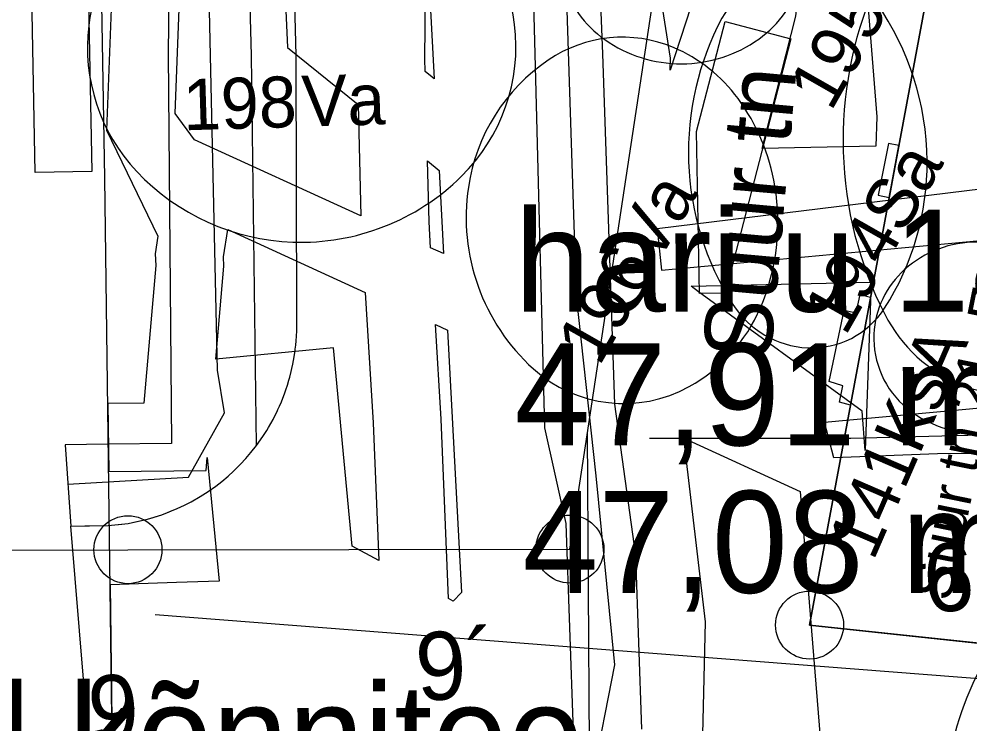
# Model space of a CAD drawing. Extents: x 738423 to 738903, y 6589762 to 6590172.
# Drawn here: x 738562.92 to 738590.9, y 6589869.71 to 6589890.45 of the extents above; entities that cross this region are included whole.
import ezdxf

# ---------------------------------------------------------------- set-up
doc = ezdxf.new("R2010")
doc.units = 0
for name, color, linetype in [('_1927_hoonestus', 7, 'Continuous'), ('_1927_katuse_kalded', 7, 'Continuous'), ('_1927_koordin_punktid_nr', 7, 'Continuous'), ('_1927_krundi_piir', 7, 'Continuous'), ('_a_ajalooline_maapind', 7, 'Continuous'), ('_a_olol_maapind', 7, 'Continuous'), ('_ajalooline_aadress', 7, 'Continuous'), ('a_', 7, 'Continuous'), ('a_dendro_II_Vkl_puu', 7, 'Continuous'), ('a_dendro_III_vk_puu', 7, 'Continuous'), ('a_dendro_puu_nr', 7, 'Continuous'), ('Default', 7, 'Continuous'), ('plan_ala', 7, 'Continuous'), ('v_dp_jalak_liikumine', 7, 'Continuous'), ('v_dp_tehno_sund', 7, 'Continuous'), ('v_olol_hoone', 7, 'Continuous'), ('v_olol_kitsendus_tehnov', 7, 'Continuous'), ('v_olol_transp_jjt_jalg', 7, 'Continuous'), ('v_olol_transp_tee', 7, 'Continuous')]:
    doc.layers.add(name, color=color, linetype=linetype)

# ---------------------------------------------------------------- blocks, each defined once
blk = doc.blocks.new('_U589')
at = {"layer": 'Default'}
for centre, radius, start, end in [((-3.0332052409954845e-05, -0.002338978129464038), 0.01836532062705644, 93.86605779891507, 141.50719662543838), ((-4.742218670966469e-05, -0.0020860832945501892), 0.018111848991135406, 48.095809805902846, 93.86605779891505), ((0.00495080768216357, 0.003483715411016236), 0.010628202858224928, 347.0797159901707, 48.09580980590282), ((-0.006053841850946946, 0.0024511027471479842), 0.01066937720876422, 141.5071966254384, 205.50153110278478), ((0.003081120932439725, 0.003912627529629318), 0.012546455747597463, 307.30050710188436, 347.0797159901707), ((-0.004183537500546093, 0.0033432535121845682), 0.012741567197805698, 205.50153110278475, 244.5264522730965), ((-0.0011840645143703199, 0.009511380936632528), 0.019584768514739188, 275.69820016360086, 307.30050710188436), ((-0.0011946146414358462, 0.009617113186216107), 0.019691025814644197, 244.52645227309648, 275.69820016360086)]:
    blk.add_arc(centre, radius, start, end, dxfattribs=at)
blk = doc.blocks.new('_U591')
at = {"layer": 'Default'}
for centre, radius, start, end in [((-0.0003541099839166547, 0.0006764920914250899), 0.005338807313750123, 91.75356257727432, 144.94764571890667), ((-0.00035206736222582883, 0.0006097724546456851), 0.0054055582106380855, 45.990503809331, 91.75356257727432), ((-0.001037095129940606, -9.935932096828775e-05), 0.006391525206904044, 4.0870855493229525, 45.99050380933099), ((0.0005026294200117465, 7.542928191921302e-05), 0.006385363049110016, 144.94764571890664, 193.2797082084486), ((-0.0009608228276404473, -9.390933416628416e-05), 0.00631505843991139, 322.4423423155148, 4.08708554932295), ((0.00038141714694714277, 4.682123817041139e-05), 0.006260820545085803, 193.27970820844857, 233.32322588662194), ((-0.00018547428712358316, -0.0006900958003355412), 0.005336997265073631, 276.9468734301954, 322.4423423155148), ((-0.0001829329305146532, -0.000710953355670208), 0.0053159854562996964, 233.3232258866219, 276.9468734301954)]:
    blk.add_arc(centre, radius, start, end, dxfattribs=at)
blk = doc.blocks.new('_U643')
at = {"layer": 'Default'}
for centre, radius, start, end in [((0.001839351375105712, -0.01638537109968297), 0.02252182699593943, 96.00680549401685, 121.28846409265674), ((0.0018679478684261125, -0.01665713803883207), 0.02279509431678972, 71.14771462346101, 96.00680549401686), ((0.0062500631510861, -0.0038231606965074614), 0.009233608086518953, 31.614909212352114, 71.14771462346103), ((-0.005254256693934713, -0.004713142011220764), 0.008863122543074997, 121.28846409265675, 162.12182872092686), ((0.009030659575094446, -0.0021115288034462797), 0.005968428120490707, 314.530794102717, 31.614909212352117), ((-0.008067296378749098, -0.00380573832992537), 0.00590735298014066, 162.12182872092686, 235.6485071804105), ((-0.000617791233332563, 0.007696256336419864), 0.019726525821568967, 274.44396782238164, 314.530794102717), ((-0.0005757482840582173, 0.0071552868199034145), 0.019183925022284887, 235.6485071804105, 274.44396782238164)]:
    blk.add_arc(centre, radius, start, end, dxfattribs=at)
blk = doc.blocks.new('_U644')
at = {"layer": 'Default'}
for centre, radius, start, end in [((0.001280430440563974, -0.010476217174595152), 0.01658674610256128, 96.22277175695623, 126.90463232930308), ((0.00130196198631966, -0.010673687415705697), 0.016785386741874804, 66.2630147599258, 96.22277175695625), ((0.005749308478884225, -0.0005600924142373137), 0.005737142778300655, 13.784006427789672, 66.26301475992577), ((-0.005344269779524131, -0.001654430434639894), 0.005554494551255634, 126.90463232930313, 181.31501957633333), ((0.006382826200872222, -0.0004046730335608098), 0.005084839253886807, 309.3713168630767, 13.784006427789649), ((-0.00581699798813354, -0.001665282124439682), 0.005081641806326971, 181.3150195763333, 241.68386791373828), ((-0.0007414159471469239, 0.008277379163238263), 0.01631572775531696, 274.75209171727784, 309.37131686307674), ((-0.000703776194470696, 0.007824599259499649), 0.015861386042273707, 241.68386791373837, 274.75209171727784)]:
    blk.add_arc(centre, radius, start, end, dxfattribs=at)
blk = doc.blocks.new('_U645')
at = {"layer": 'Default'}
for centre, radius, start, end in [((-0.001848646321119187, 2.996627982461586e-05), 0.011998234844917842, 85.79154951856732, 142.2176902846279), ((-0.0017770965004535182, 0.0010023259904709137), 0.01102324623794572, 38.521789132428, 85.79154951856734), ((0.0007803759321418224, 0.003038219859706), 0.007754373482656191, 341.41250812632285, 38.521789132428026), ((-0.005054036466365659, 0.0025147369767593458), 0.0079425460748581, 142.21769028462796, 213.26626182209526), ((-0.00046359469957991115, 0.0034565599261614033), 0.009066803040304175, 310.5147127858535, 341.41250812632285), ((-0.003640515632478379, 0.003442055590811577), 0.00963309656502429, 213.2662618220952, 251.166227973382), ((-0.0024438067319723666, 0.0057738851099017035), 0.0121149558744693, 283.86825920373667, 310.5147127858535), ((-0.0026123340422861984, 0.006456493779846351), 0.01281806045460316, 251.16622797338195, 283.86825920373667)]:
    blk.add_arc(centre, radius, start, end, dxfattribs=at)
blk = doc.blocks.new('_U646')
at = {"layer": 'Default'}
for centre, radius, start, end in [((0.0015413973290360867, 0.0003312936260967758), 0.0060430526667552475, 57.797497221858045, 109.91963154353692), ((0.0016638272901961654, -6.553680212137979e-06), 0.006402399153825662, 109.91963154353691, 149.09162520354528), ((0.0007475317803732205, -0.000929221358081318), 0.007532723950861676, 11.452907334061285, 57.79749722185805), ((0.0028668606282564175, -0.000726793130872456), 0.007804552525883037, 149.09162520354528, 184.44182767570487), ((0.0005947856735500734, -0.0009601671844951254), 0.007688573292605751, 318.66315817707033, 11.452907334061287), ((0.0029452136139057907, -0.0007207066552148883), 0.00788314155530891, 184.44182767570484, 219.7138265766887), ((0.001892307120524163, -0.0015952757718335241), 0.006514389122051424, 219.71382657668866, 258.64991313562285), ((0.0018059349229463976, -0.002025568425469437), 0.006075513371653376, 258.64991313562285, 318.66315817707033)]:
    blk.add_arc(centre, radius, start, end, dxfattribs=at)
blk = doc.blocks.new('_U647')
at = {"layer": 'Default'}
for centre, radius, start, end in [((-0.001375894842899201, 0.00038972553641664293), 0.01064500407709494, 87.41040859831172, 137.64698014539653), ((-0.0013903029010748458, 7.115839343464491e-05), 0.01096389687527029, 46.91324083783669, 87.4104085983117), ((-0.003055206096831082, -0.0017088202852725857), 0.013401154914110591, 10.427707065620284, 46.91324083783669), ((0.0005566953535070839, -0.0013720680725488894), 0.013260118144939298, 137.64698014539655, 182.35571578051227), ((-0.0033161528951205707, -0.0017568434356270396), 0.013666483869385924, 328.31163123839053, 10.427707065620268), ((0.0007803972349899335, -0.0013628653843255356), 0.013484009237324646, 182.3557157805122, 228.78056258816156), ((-0.0010775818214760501, -0.003138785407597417), 0.011035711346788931, 281.1734997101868, 328.3116312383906), ((-0.0010219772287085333, -0.0034202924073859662), 0.010748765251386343, 228.7805625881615, 281.1734997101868)]:
    blk.add_arc(centre, radius, start, end, dxfattribs=at)

msp = doc.modelspace()

# ---------------------------------------------------------------- linework, layer by layer
at = {"layer": '_1927_hoonestus'}
for points in [[(738598.7561479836, 6589884.064893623), (738598.7561479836, 6589884.064893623), (738600.1654182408, 6589891.510843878), (738617.1576277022, 6589889.916511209), (738616.9587005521, 6589887.781161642), (738616.9587005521, 6589887.781161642), (738621.4793553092, 6589887.4869466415), (738621.2187353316, 6589884.178665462), (738631.1763472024, 6589883.225550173), (738634.3211426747, 6589909.080822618), (738624.2071897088, 6589909.313105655), (738622.5673353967, 6589895.324185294), (738590.9372064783, 6589898.13516685), (738590.9372064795, 6589898.13516685), (738586.1827055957, 6589872.62061175), (738613.3249623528, 6589869.722398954), (738613.2710881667, 6589869.728151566), (738614.3523733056, 6589877.812429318), (738614.3523733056, 6589877.812429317), (738614.3523733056, 6589877.812429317), (738615.0233334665, 6589882.235576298)], [(738588.8127019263, 6589886.73422492), (738588.5070185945, 6589886.794471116), (738588.1986895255, 6589885.274121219), (738588.527742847, 6589885.205020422)], [(738587.388382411, 6589879.090756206), (738587.0612662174, 6589879.175962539), (738587.1642145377, 6589879.657378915), (738586.7650323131, 6589879.784371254), (738587.1979710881, 6589881.885807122), (738587.5573741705, 6589881.811762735), (738587.6678450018, 6589882.347975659), (738587.9811086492, 6589882.271562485)]]:
    msp.add_lwpolyline(points, close=True, dxfattribs=at)
at = {"layer": '_1927_katuse_kalded'}
msp.add_lwpolyline([(738586.1827055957, 6589872.62061175), (738591.5884234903, 6589872.043396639), (738595.5346271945, 6589892.346110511), (738589.9993202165, 6589893.102093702)], close=True, dxfattribs=at)
at = {"layer": '_1927_koordin_punktid_nr'}
for centre in [(738566.1261897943, 6589874.839209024), (738579.1301963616, 6589874.856906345), (738586.182705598, 6589872.620611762)]:
    msp.add_circle(centre, 0.9999999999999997, dxfattribs=at)
at = {"layer": '_1927_krundi_piir'}
msp.add_line((738629.2817413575, 6589868.018556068), (738586.182705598, 6589872.620611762), dxfattribs=at)
for points in [[(738579.1301963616, 6589874.856906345), (738582.2977970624, 6589895.764005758), (738583.8997575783, 6589916.874257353), (738587.3009719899, 6589941.27260649), (738586.2348708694, 6589945.684910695), (738584.5188972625, 6589952.81209349)], [(738586.182705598, 6589872.620611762), (738590.9372064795, 6589898.13516685), (738590.975352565, 6589898.488217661), (738593.7110525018, 6589923.115674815), (738595.6482555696, 6589940.609766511), (738608.5799562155, 6589940.823351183), (738620.342268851, 6589941.795771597), (738638.2396178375, 6589940.94571321)], [(738456.3718778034, 6589873.590089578), (738496.3572965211, 6589874.745766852), (738517.6969158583, 6589874.771193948), (738536.6717751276, 6589874.799754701), (738566.1261897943, 6589874.839209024), (738579.1301963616, 6589874.856906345)]]:
    msp.add_lwpolyline(points, dxfattribs=at)
at = {"layer": 'a_'}
for p, q in [((738579.7240658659, 6589866.182764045), (738579.6493548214, 6589878.283505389)), ((738566.9298928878, 6589872.9281633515), (738595.2945655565, 6589870.727518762))]:
    msp.add_line(p, q, dxfattribs=at)
at = {"layer": 'Default'}
for points in [[(738581.2509999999, 6589869.558000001), (738581.073, 6589874.656), (738580.457, 6589879.119), (738580.1019999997, 6589889.433000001), (738579.5900000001, 6589902.219999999), (738580.555, 6589902.854999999), (738586.5010000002, 6589903.156999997), (738587.2448897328, 6589903.302988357), (738587.463427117, 6589905.386079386), (738586.2330000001, 6589905.318), (738580.2700000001, 6589904.839), (738579.4450000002, 6589905.446999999), (738579.2310000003, 6589922.173000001)], [(738577.3480000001, 6589920.061000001), (738577.716, 6589903.953000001), (738578.12, 6589888.683000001), (738578.3879999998, 6589878.424000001), (738579.014, 6589875.606999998), (738579.2310000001, 6589869.493000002)]]:
    msp.add_lwpolyline(points, dxfattribs=at)
at = {"layer": 'plan_ala'}
msp.add_lwpolyline([(738772.2221966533, 6589837.873120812), (738583.11, 6589865.669999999), (738583.11, 6589865.669999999), (738577.13, 6589865.85), (738565.7035831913, 6589866.139410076), (738565.4500000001, 6589885.77), (738564.4932191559, 6589941.052825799), (738581.9, 6589941.1499999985), (738615.11, 6589942.169999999), (738650.0499999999, 6589943.319999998), (738691.2690631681, 6589944.800325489), (738696.0901513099, 6589944.851371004), (738713.89, 6589945.129999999), (738703.51, 6589987.789999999), (738752.8799999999, 6590000.39), (738783.1408503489, 6590007.463828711), (738767.5688789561, 6589951.87996157)], close=True, dxfattribs=at)
at = {"layer": 'v_dp_jalak_liikumine'}
for points in [[(738580.8222069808, 6589853.375742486), (738579.8731274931, 6589862.502301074), (738579.7948247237, 6589868.094183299), (738580.455907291, 6589871.452329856), (738579.9085136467, 6589877.0110812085), (738579.325053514, 6589882.302804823), (738578.6922566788, 6589901.835364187), (738578.2534358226, 6589923.78491095), (738577.7643827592, 6589940.522382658), (738578.0100246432, 6589944.392285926), (738576.7151896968, 6589950.204053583)], [(738564.3587612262, 6589876.768792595), (738567.9129245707, 6589876.968967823), (738568.9682240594, 6589878.865942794), (738568.76067344, 6589880.123714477), (738568.2947477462, 6589901.299299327), (738567.7091425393, 6589926.873099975), (738566.992151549, 6589942.227474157), (738566.338151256, 6589947.998374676)], [(738581.4723412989, 6589878.120522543), (738587.4015406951, 6589878.120522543), (738606.5184403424, 6589878.608756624), (738618.5434188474, 6589878.425595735), (738641.8496480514, 6589878.136204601), (738655.9728153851, 6589879.813491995), (738670.3230528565, 6589879.497843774), (738680.5529887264, 6589878.338003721), (738697.9581193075, 6589880.397873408), (738705.6932562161, 6589881.082962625), (738725.5888177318, 6589880.833839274), (738742.0007790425, 6589880.833839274), (738745.4047050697, 6589880.7783847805), (738754.5304628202, 6589882.343075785), (738758.8441211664, 6589885.746853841)]]:
    msp.add_lwpolyline(points, dxfattribs=at)
at = {"layer": 'v_dp_tehno_sund'}
msp.add_lwpolyline([(738585.63220001, 6589889.873199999), (738583.6956, 6589882.391), (738582.94000001, 6589882.38), (738582.8558, 6589887.1405), (738583.6967, 6589890.3771)], close=True, dxfattribs=at)
at = {"layer": 'v_olol_hoone'}
msp.add_lwpolyline([(738563.1864886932, 6589896.902176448), (738564.8460000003, 6589896.936000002), (738565.0596708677, 6589885.967899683), (738563.3941039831, 6589885.935452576)], close=True, dxfattribs=at)
at = {"layer": 'v_olol_kitsendus_tehnov'}
for points in [[(738567.6884596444, 6589928.157698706), (738569.5640555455, 6589928.107424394), (738569.7442949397, 6589922.973568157), (738570.2308726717, 6589902.597054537), (738570.8235144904, 6589889.61800687), (738572.8972610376, 6589887.936315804), (738572.9818196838, 6589884.664234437), (738568.089969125, 6589886.902320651), (738567.5159941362, 6589887.676248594), (738567.8866814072, 6589897.433658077), (738567.9899137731, 6589898.018834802), (738568.721228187, 6589898.636862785), (738568.6597970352, 6589921.868076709)], [(738582.0806785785, 6589888.9498845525), (738582.0888304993, 6589889.297274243), (738581.1487846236, 6589895.290815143), (738581.3691582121, 6589899.835374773), (738582.3698831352, 6589899.926173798), (738582.3430488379, 6589901.192727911), (738583.3139503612, 6589901.241959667), (738583.6007202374, 6589893.6200148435)], [(738574.904547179, 6589893.1154798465), (738575.1393173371, 6589888.692995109), (738575.0823527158, 6589888.739309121), (738574.8727855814, 6589888.909256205), (738574.8631395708, 6589889.282518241)], [(738575.0337955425, 6589883.725428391), (738574.9872051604, 6589884.4816761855), (738574.9408154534, 6589886.276772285), (738575.2823234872, 6589885.999115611), (738575.4122142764, 6589883.552296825)], [(738572.1726483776, 6589880.774872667), (738568.713804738, 6589880.446204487), (738568.9528174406, 6589883.178554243), (738568.9351775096, 6589883.451973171), (738569.0649967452, 6589884.25685243), (738573.1113141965, 6589882.405608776), (738573.3472319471, 6589878.576228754), (738573.5098466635, 6589874.51818583), (738572.7267045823, 6589874.9440868)], [(738587.9947308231, 6589882.710662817), (738587.8201164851, 6589877.754352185), (738587.7269088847, 6589878.910557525), (738582.912444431, 6589882.422678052), (738582.6979742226, 6589882.5943622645)], [(738575.6968588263, 6589873.328809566), (738575.5560439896, 6589873.405389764), (738575.344768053, 6589878.677771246), (738575.1732233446, 6589881.462258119), (738575.5318759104, 6589881.298169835), (738575.9417934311, 6589873.576345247)]]:
    msp.add_lwpolyline(points, close=True, dxfattribs=at)
for points in [[(738564.7836066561, 6589924.311755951), (738565.5546792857, 6589898.442616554), (738565.977184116, 6589898.121736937), (738565.8933185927, 6589897.646341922), (738565.4958801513, 6589887.184775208), (738567.007573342, 6589884.061082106), (738566.9248224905, 6589883.548026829), (738566.9471825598, 6589883.201445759), (738566.5929069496, 6589879.151431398), (738565.5356253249, 6589879.141502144), (738565.5614588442, 6589877.14165656), (738568.4270930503, 6589877.168568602), (738568.4607498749, 6589877.553327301), (738568.8064016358, 6589873.915751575), (738567.5534011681, 6589873.878412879), (738565.6046055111, 6589873.801551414), (738565.6869613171, 6589867.426156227)], [(738591.66193984, 6589894.040728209), (738588.6389999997, 6589893.962), (738587.6660926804, 6589893.829031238), (738588.1662590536, 6589887.579376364), (738588.135796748, 6589886.714724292), (738584.7931808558, 6589886.641330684), (738585.7810944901, 6589890.54142003), (738586.1426695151, 6589893.750789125), (738586.0517247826, 6589901.380784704), (738588.4926106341, 6589901.504555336), (738588.4591681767, 6589903.227642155), (738587.933124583, 6589903.217432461), (738587.889229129, 6589905.479098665), (738585.9959303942, 6589905.383094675), (738585.9826741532, 6589905.560547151), (738587.8870005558, 6589905.593923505), (738587.8850000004, 6589905.697), (738588.4110435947, 6589905.707209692), (738588.3392058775, 6589909.602463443)], [(738582.957333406, 6589865.674595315), (738583.1203691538, 6589872.717573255), (738582.4794695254, 6589878.119554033), (738585.9107412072, 6589876.549701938), (738586.6978541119, 6589866.78586143)]]:
    msp.add_lwpolyline(points, dxfattribs=at)
at = {"layer": 'v_olol_transp_jjt_jalg'}
for points in [[(738581.2509999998, 6589869.558000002), (738581.073, 6589874.656), (738580.4569999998, 6589879.118999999), (738580.102, 6589889.433000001), (738579.5900000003, 6589902.219999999), (738580.555, 6589902.854999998), (738586.5010000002, 6589903.157000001), (738587.3010000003, 6589903.313999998), (738587.2610015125, 6589905.374879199), (738586.2329999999, 6589905.317999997), (738580.2699999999, 6589904.838999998), (738579.445, 6589905.446999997), (738579.2310000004, 6589922.1729999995)], [(738577.3479999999, 6589920.061), (738577.7159999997, 6589903.953), (738578.1199999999, 6589888.682999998), (738578.3879999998, 6589878.423999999), (738579.0140000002, 6589875.607), (738579.2310000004, 6589869.493000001)], [(738567.4200000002, 6589899.302000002), (738567.308, 6589889.425), (738567.4120000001, 6589877.964000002), (738565.5350274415, 6589877.942673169), (738564.2760718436, 6589877.9283684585), (738564.4467826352, 6589875.534444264), (738565.5440000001, 6589875.547000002), (738565.9454704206, 6589875.586374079), (738566.1317947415, 6589875.614088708), (738566.3931792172, 6589875.670514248), (738566.7004281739, 6589875.736840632), (738566.8687682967, 6589875.7887755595), (738567.1261730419, 6589875.868187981), (738567.2742066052, 6589875.926941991), (738567.4296404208, 6589875.988633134), (738567.5781354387, 6589876.047570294), (738567.791011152, 6589876.147440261), (738567.9871197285, 6589876.2488150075), (738568.2563765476, 6589876.403662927), (738568.4855327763, 6589876.550888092), (738568.7119822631, 6589876.711680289), (738568.8879156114, 6589876.848119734), (738569.0749685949, 6589877.005355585), (738569.2315573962, 6589877.147604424), (738569.3353643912, 6589877.250340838), (738569.4416940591, 6589877.355573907), (738569.5986054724, 6589877.525307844), (738569.743375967, 6589877.694454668), (738569.9119999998, 6589877.909), (738569.7619999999, 6589889.376999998), (738569.4820219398, 6589900.016635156)]]:
    msp.add_lwpolyline(points, dxfattribs=at)
for points in [[(738581.6950000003, 6589884.280999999), (738581.8219999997, 6589883.063999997), (738591.5299999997, 6589883.9679999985), (738608.3539999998, 6589886.010999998), (738615.5839999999, 6589886.649999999), (738615.4390000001, 6589888.155999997), (738608.0640000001, 6589887.33), (738591.8460000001, 6589885.529)], [(738608.1226609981, 6589880.056703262), (738609.449, 6589880.072000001), (738610.0780826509, 6589880.024413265), (738610.0780826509, 6589880.024413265), (738610.195, 6589876.471000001), (738608.6379999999, 6589876.482999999), (738608.6379999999, 6589876.482999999), (738608.2503136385, 6589876.487158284), (738608.2503136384, 6589876.487158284), (738608.1189999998, 6589877.699999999), (738608.1192188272, 6589877.747777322), (738589.9439999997, 6589877.660999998), (738586.8979999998, 6589877.539000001), (738586.624, 6589878.5869999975), (738594.5109999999, 6589879.317999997), (738602.754, 6589879.872), (738608.1242055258, 6589879.365527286)]]:
    msp.add_lwpolyline(points, close=True, dxfattribs=at)
at = {"layer": 'v_olol_transp_tee'}
for points in [[(738577.3479999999, 6589920.061), (738577.7159999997, 6589903.953), (738578.1199999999, 6589888.682999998), (738578.3879999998, 6589878.423999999), (738579.0140000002, 6589875.607), (738579.2310000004, 6589869.493000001)], [(738564.9604277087, 6589869.373161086), (738564.4467826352, 6589875.534444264), (738564.8583281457, 6589875.539153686), (738565.5439999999, 6589875.547), (738566.1317946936, 6589875.614088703), (738566.7004281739, 6589875.736840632), (738567.1261730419, 6589875.868187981), (738567.5781354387, 6589876.047570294), (738567.791011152, 6589876.147440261), (738567.9871197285, 6589876.2488150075), (738568.2563765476, 6589876.403662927), (738568.4855327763, 6589876.550888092), (738568.7119822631, 6589876.711680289), (738568.8879156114, 6589876.848119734), (738569.0749685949, 6589877.005355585), (738569.2315573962, 6589877.147604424), (738569.4416940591, 6589877.355573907), (738569.5986054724, 6589877.525307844), (738569.743375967, 6589877.694454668), (738569.9119999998, 6589877.909), (738570.0273962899, 6589878.068432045), (738570.1136574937, 6589878.1953384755), (738570.2117711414, 6589878.348852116), (738570.2640456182, 6589878.435112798), (738570.3305321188, 6589878.549862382), (738570.3958284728, 6589878.668671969), (738570.452323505, 6589878.776977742), (738570.5171491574, 6589878.908433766), (738570.5421125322, 6589878.961342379), (738570.5871630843, 6589879.060423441), (738570.6437903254, 6589879.192346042), (738570.684751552, 6589879.293679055), (738570.7342187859, 6589879.423840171), (738570.7762723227, 6589879.542406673), (738570.8204787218, 6589879.676555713), (738570.8653812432, 6589879.8252220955), (738570.8892277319, 6589879.910467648), (738570.9323083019, 6589880.078721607), (738570.9538449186, 6589880.171545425), (738570.9810588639, 6589880.299927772), (738571.0020215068, 6589880.409885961), (738571.02038953, 6589880.517032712), (738571.0392880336, 6589880.642121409), (738571.051721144, 6589880.736288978), (738571.0653998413, 6589880.856780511), (738571.0768989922, 6589880.981015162), (738571.0866724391, 6589881.120416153), (738571.0936776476, 6589881.275571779), (738571.0965060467, 6589881.415274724), (738571.0963368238, 6589881.532729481), (738571.0939999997, 6589881.644999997), (738571.0769999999, 6589889.378), (738570.8110000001, 6589899.744)]]:
    msp.add_lwpolyline(points, dxfattribs=at)

# ---------------------------------------------------------------- block references
at = {"layer": 'a_dendro_II_Vkl_puu', "xscale": 500.0000000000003, "yscale": 500.0000000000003, "rotation": 85.69234851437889}
msp.add_blockref('_U643', (738590.191, 6589886.574999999), dxfattribs=at)
at = {"layer": 'a_dendro_III_vk_puu', "xscale": 500.0000000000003, "yscale": 500.0000000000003, "rotation": 85.69234851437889}
for name, p in [('_U646', (738581.9369999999, 6589891.635)), ('_U647', (738570.5030000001, 6589890.29)), ('_U644', (738585.6409999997, 6589886.279)), ('_U645', (738582.1609999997, 6589885.537000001)), ('_U591', (738591.0953105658, 6589881.216442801)), ('_U589', (738598.176, 6589867.216))]:
    msp.add_blockref(name, p, dxfattribs=at)

# ---------------------------------------------------------------- texts
at = {"layer": '_1927_koordin_punktid_nr'}
for s, height, rotation, p in [('Suur tn', 1.9999999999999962, 84.83058672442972, (738585.023061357, 6589880.3657192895)), ('6', 1.9999999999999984, 3.560863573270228, (738589.5909850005, 6589872.985900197)), ('9´', 1.9999999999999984, 3.560863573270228, (738574.6550161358, 6589870.381702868)), ('9', 1.9999999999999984, 3.560863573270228, (738565.0167192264, 6589869.107865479))]:
    msp.add_text(s, height=height, rotation=rotation, dxfattribs=at).set_placement(p)
at = {"layer": '_a_ajalooline_maapind'}
msp.add_text('47,08 m', height=3, dxfattribs=at).set_placement((738577.7330276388, 6589873.569741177))
at = {"layer": '_a_olol_maapind'}
for s, p in [('hari u 18 m', (738577.5007601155, 6589881.843884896)), ('47,91 m', (738577.5007601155, 6589877.90741173)), ('olol kõnnitee', (738557.0146249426, 6589867.880322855))]:
    msp.add_text(s, height=3, dxfattribs=at).set_placement(p)
at = {"layer": '_ajalooline_aadress'}
msp.add_text('Suur tn 21, Fonne maja', height=1.2, rotation=78.52821347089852, dxfattribs=at).set_placement((738590.3305469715, 6589873.2898918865))
at = {"layer": 'a_dendro_puu_nr'}
for s, height, rotation, p in [('5Sa', 1.4999999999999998, 60.34715687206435, (738587.9634097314, 6589889.728261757)), ('19', 1.4999999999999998, 60.34715687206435, (738586.8102454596, 6589887.702677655)), ('198', 1.5, 1.7381147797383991, (738567.7671022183, 6589887.176266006)), ('Va', 1.5, 1.7381147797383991, (738571.2617419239, 6589887.28231132)), ('4Sa', 1.4999999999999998, 60.34715687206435, (738588.3873181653, 6589883.120558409)), ('6Va', 1.4999999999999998, 60.34715687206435, (738581.144854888, 6589882.228429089)), ('19', 1.4999999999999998, 60.34715687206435, (738587.2341538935, 6589881.094974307)), ('19', 1.4999999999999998, 60.34715687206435, (738579.9916906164, 6589880.202844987)), ('41KsA', 1.5000000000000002, 66.56774415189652, (738588.5216379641, 6589875.5488337)), ('1', 1.5000000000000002, 66.56774415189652, (738588.0581933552, 6589874.479528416))]:
    msp.add_text(s, height=height, rotation=rotation, dxfattribs=at).set_placement(p)

doc.saveas('drawing.dxf')
